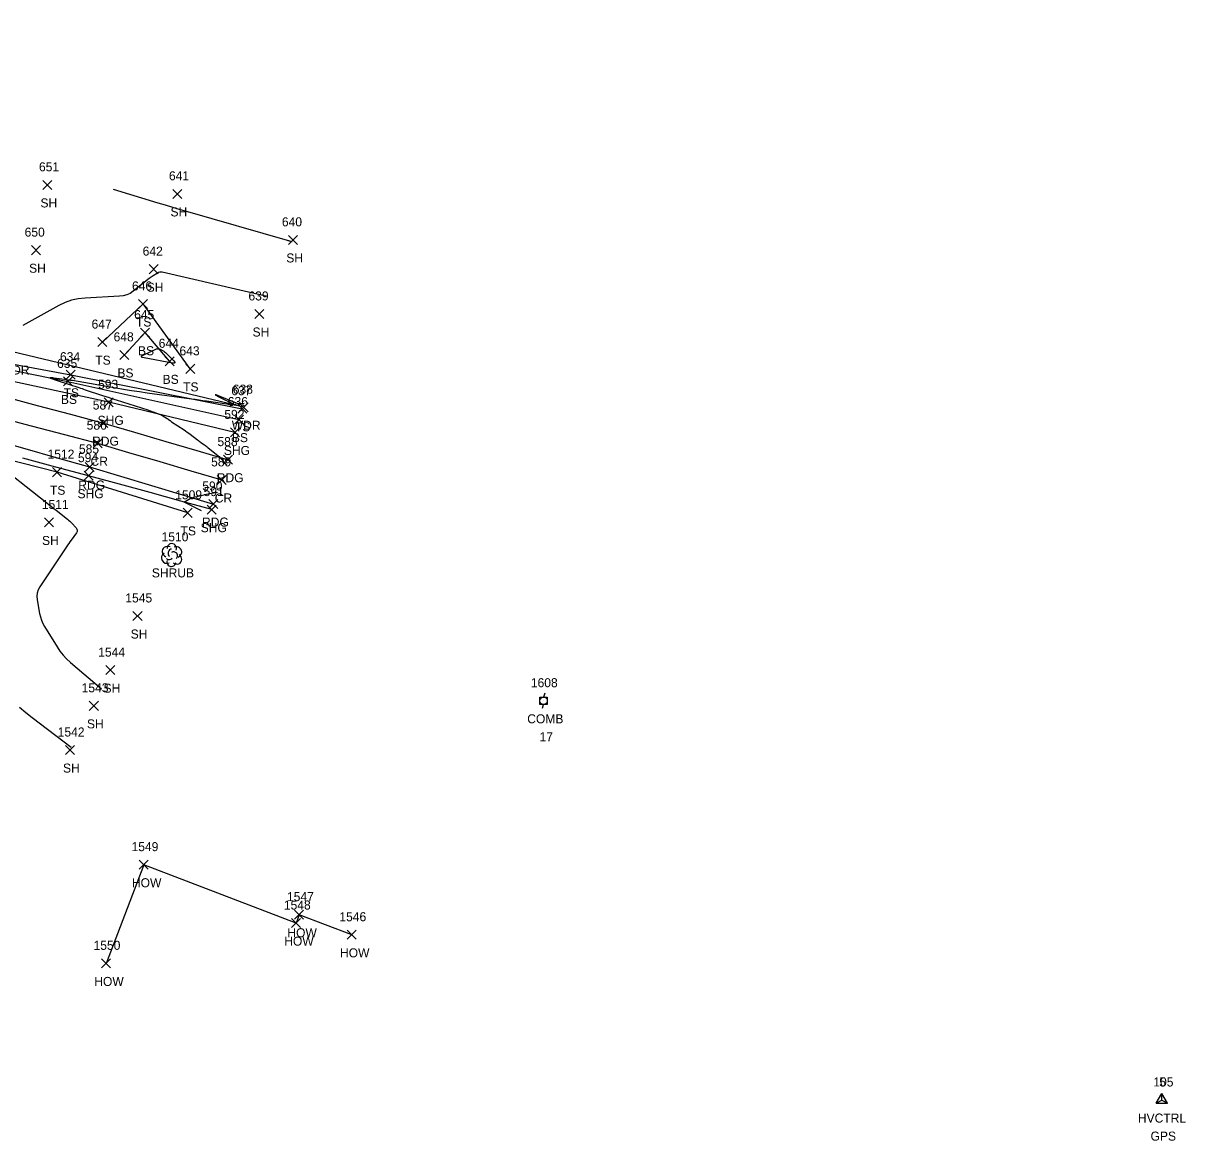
# Model space of a CAD drawing. Extents: x 1592612 to 1596497, y 111838 to 113741.
# Drawn here: x 1593120.8 to 1593378.4, y 113212.6 to 113460.3 of the extents above; entities that cross this region are included whole.
import ezdxf

# ---------------------------------------------------------------- set-up
doc = ezdxf.new("R2010")
doc.units = 0
for name, color, linetype in [('C_A', 7, 'Continuous'), ('C_C', 7, 'Continuous'), ('C_I', 7, 'Continuous'), ('CPSM', 7, 'Continuous'), ('L_A', 7, 'Continuous'), ('L_I', 7, 'Continuous'), ('L_TIC', 7, 'Continuous'), ('LAWA', 7, 'Continuous'), ('LBC', 7, 'Continuous'), ('LELB', 7, 'Continuous'), ('LSH', 7, 'Continuous'), ('LSOGCMA', 7, 'Continuous'), ('LSOGCMI', 7, 'Continuous'), ('P_A', 7, 'Continuous'), ('P_I', 7, 'Continuous'), ('P_TIC', 7, 'Continuous'), ('PEU', 7, 'Continuous'), ('PRC', 7, 'Continuous'), ('PSU', 7, 'Continuous'), ('U_A', 7, 'Continuous'), ('U_C', 7, 'Continuous'), ('U_I', 7, 'Continuous'), ('UP', 7, 'Continuous')]:
    doc.layers.add(name, color=color, linetype=linetype)

msp = doc.modelspace()

# ---------------------------------------------------------------- linework, layer by layer
at = {"layer": 'CPSM'}
for p, q in [((1593371.86, 113220.91), (1593373.11, 113223.08)), ((1593371.86, 113220.91), (1593373.11, 113223.08)), ((1593374.36, 113220.91), (1593373.11, 113223.08)), ((1593373.11, 113221.63), (1593373.11, 113223.08)), ((1593374.36, 113220.91), (1593373.11, 113223.08)), ((1593373.11, 113221.63), (1593373.11, 113223.08)), ((1593371.86, 113220.91), (1593373.11, 113221.63)), ((1593371.86, 113220.91), (1593373.11, 113221.63)), ((1593371.86, 113220.91), (1593374.36, 113220.91)), ((1593371.86, 113220.91), (1593374.36, 113220.91)), ((1593373.11, 113221.63), (1593373.11, 113221.63)), ((1593373.11, 113221.63), (1593374.36, 113220.91)), ((1593373.11, 113221.63), (1593373.11, 113221.63)), ((1593373.11, 113221.63), (1593374.36, 113220.91))]:
    msp.add_line(p, q, dxfattribs=at)
at = {"layer": 'L_TIC'}
for points in [[(1593125.09, 113423.44), (1593127.09, 113425.44)], [(1593127.09, 113423.44), (1593125.09, 113425.44)], [(1593153.9, 113421.45), (1593155.9, 113423.45)], [(1593155.9, 113421.45), (1593153.9, 113423.45)], [(1593179.57, 113411.25), (1593181.57, 113413.25)], [(1593181.57, 113411.25), (1593179.57, 113413.25)], [(1593122.56, 113408.97), (1593124.56, 113410.97)], [(1593124.56, 113408.97), (1593122.56, 113410.97)], [(1593148.63, 113404.76), (1593150.63, 113406.76)], [(1593150.63, 113404.76), (1593148.63, 113406.76)], [(1593146.33, 113397.05), (1593148.33, 113399.05)], [(1593148.33, 113397.05), (1593146.33, 113399.05)], [(1593172.09, 113394.83), (1593174.09, 113396.83)], [(1593174.09, 113394.83), (1593172.09, 113396.83)], [(1593146.75, 113390.69), (1593148.75, 113392.69)], [(1593148.75, 113390.69), (1593146.75, 113392.69)], [(1593137.31, 113388.59), (1593139.31, 113390.59)], [(1593139.31, 113388.59), (1593137.31, 113390.59)], [(1593142.19, 113385.76), (1593144.19, 113387.76)], [(1593144.19, 113385.76), (1593142.19, 113387.76)], [(1593152.19, 113384.34), (1593154.19, 113386.34)], [(1593154.19, 113384.34), (1593152.19, 113386.34)], [(1593156.78, 113382.67), (1593158.78, 113384.67)], [(1593158.78, 113382.67), (1593156.78, 113384.67)], [(1593129.66, 113379.88), (1593131.66, 113381.88)], [(1593131.66, 113379.88), (1593129.66, 113381.88)], [(1593130.3, 113381.36), (1593132.3, 113383.36)], [(1593132.3, 113381.36), (1593130.3, 113383.36)], [(1593168.28, 113373.83), (1593170.28, 113375.83)], [(1593170.28, 113373.83), (1593168.28, 113375.83)], [(1593168.61, 113374.17), (1593170.61, 113376.17)], [(1593170.61, 113374.17), (1593168.61, 113376.17)], [(1593167.55, 113371.43), (1593169.55, 113373.43)], [(1593169.55, 113371.43), (1593167.55, 113373.43)], [(1593127.27, 113359.77), (1593129.27, 113361.77)], [(1593129.27, 113359.77), (1593127.27, 113361.77)], [(1593125.43, 113348.63), (1593127.43, 113350.63)], [(1593127.43, 113348.63), (1593125.43, 113350.63)], [(1593156.22, 113350.76), (1593158.22, 113352.76)], [(1593158.22, 113350.76), (1593156.22, 113352.76)], [(1593145.08, 113327.9), (1593147.08, 113329.9)], [(1593147.08, 113327.9), (1593145.08, 113329.9)], [(1593139.06, 113315.9), (1593141.06, 113317.9)], [(1593141.06, 113315.9), (1593139.06, 113317.9)], [(1593135.4, 113307.99), (1593137.4, 113309.99)], [(1593137.4, 113307.99), (1593135.4, 113309.99)], [(1593130.09, 113298.19), (1593132.09, 113300.19)], [(1593132.09, 113298.19), (1593130.09, 113300.19)], [(1593146.46, 113272.78), (1593148.46, 113274.78)], [(1593148.46, 113272.78), (1593146.46, 113274.78)], [(1593180.9, 113261.7), (1593182.9, 113263.7)], [(1593182.9, 113261.7), (1593180.9, 113263.7)], [(1593180.21, 113259.84), (1593182.21, 113261.84)], [(1593182.21, 113259.84), (1593180.21, 113261.84)], [(1593192.57, 113257.25), (1593194.57, 113259.25)], [(1593194.57, 113257.25), (1593192.57, 113259.25)], [(1593138.12, 113250.91), (1593140.12, 113252.91)], [(1593140.12, 113250.91), (1593138.12, 113252.91)]]:
    msp.add_lwpolyline(points, dxfattribs=at)
at = {"layer": 'LAWA'}
msp.add_lwpolyline([(1593169.61, 113375.17), (1593118.4, 113387.41), (1593080.14, 113394.18), (1593050.56, 113403.45), (1593019.72, 113413.06), (1592995.66, 113420.84), (1592970.68, 113431.18), (1592941.87, 113445.58), (1592917.88, 113456.29)], dxfattribs=at)
at = {"layer": 'LBC'}
msp.add_lwpolyline([(1593193.57, 113258.25), (1593181.9, 113262.7), (1593181.21, 113260.84), (1593147.46, 113273.78), (1593139.11, 113251.91)], dxfattribs=at)
at = {"layer": 'LELB'}
for points in [[(1592908.46, 113460.26), (1592922.6, 113449.57), (1592933.27, 113441.55), (1592945.1, 113436.53), (1592970.28, 113425.51), (1592997.08, 113416.4), (1593023.64, 113407.83), (1593049.42, 113399.69), (1593079.2, 113391.84), (1593097.27, 113387.67), (1593130.66, 113380.88), (1593168.55, 113372.43)], [(1592945.37, 113437.3), (1592970.42, 113426.1), (1592997.18, 113416.81), (1593023.77, 113408.41), (1593049.59, 113400.84), (1593079.37, 113392.64), (1593097.5, 113388.59), (1593131.3, 113382.36), (1593169.28, 113374.83)], [(1593157.78, 113383.67), (1593147.33, 113398.05), (1593138.31, 113389.59)], [(1593153.19, 113385.34), (1593147.75, 113391.69), (1593143.19, 113386.76)], [(1593157.22, 113351.76), (1593128.27, 113360.77), (1593100.02, 113367.91), (1593070.22, 113374.84), (1593038.27, 113383.44), (1593013.97, 113383.15), (1593000.04, 113371.42), (1592985.82, 113350.73), (1592975.86, 113332.67)]]:
    msp.add_lwpolyline(points, dxfattribs=at)
at = {"layer": 'LSH'}
msp.add_line((1593153.62, 113342.45), (1593153.62, 113342.45), dxfattribs=at)
msp.add_line((1593153.62, 113342.45), (1593153.62, 113342.45), dxfattribs=at)
msp.add_arc((1593153.67, 113343.89), 1.05, 335.5272, 180.9563, dxfattribs=at)
for centre, major_axis, ratio, start_param, end_param in [((1593152.83, 113343.12), (1.21, -0.51), 0.895232, 1.570796, 4.712389), ((1593153.41, 113342.91), (-0.208, -0.792), 0.645439, 3.141593, 6.283185), ((1593154.12, 113342.29), (-0.5, 0.667), 0.989748, 3.141593, 6.283185), ((1593154.66, 113343.04), (-1.14, -0.48), 0.949671, 1.570796, 4.712389), ((1593152.54, 113341.75), (0.58, -1.04), 0.959034, 3.141593, 6.283185), ((1593153.62, 113340.95), (0.26, 1.06), 0.942809, 1.570796, 4.712389), ((1593153.16, 113341.7), (-0.625, -0.083), 0.423636, 0, 3.141593), ((1593154.62, 113341.62), (-1.09, 0.79), 0.841452, 1.570796, 4.712389)]:
    msp.add_ellipse(centre, major_axis=major_axis, ratio=ratio, start_param=start_param, end_param=end_param, dxfattribs=at)
at = {"layer": 'LSOGCMA'}
for points in [[(1593180.39, 113411.85), (1593179.76, 113411.99), (1593179.66, 113412.02), (1593179.55, 113412.04), (1593179.45, 113412.07), (1593179.34, 113412.1), (1593157.25, 113418.45), (1593155.59, 113418.93), (1593153.94, 113419.41), (1593152.29, 113419.91), (1593150.64, 113420.41), (1593140.75, 113423.43)], [(1593131.39, 113299.75), (1593122.75, 113306.36), (1593121.33, 113307.47), (1593119.93, 113308.62)]]:
    msp.add_lwpolyline(points, dxfattribs=at)
at = {"layer": 'LSOGCMI'}
for points in [[(1593174.85, 113399.69), (1593151.53, 113405.06), (1593151.26, 113405.1), (1593151.01, 113405.08), (1593150.76, 113405.01), (1593150.52, 113404.89), (1593149.58, 113404.31), (1593149.35, 113404.16), (1593149.12, 113404.01), (1593148.89, 113403.85), (1593148.67, 113403.68), (1593145.12, 113400.87), (1593144.43, 113400.4), (1593143.7, 113400.06), (1593142.92, 113399.84), (1593142.1, 113399.74), (1593134.46, 113399.36), (1593132.92, 113399.2), (1593131.44, 113398.87), (1593130.01, 113398.36), (1593128.62, 113397.69), (1593120.68, 113393.25)], [(1593169.75, 113376.02), (1593168.94, 113375.89), (1593168.81, 113375.87), (1593168.67, 113375.88), (1593168.54, 113375.9), (1593168.41, 113375.94), (1593164.01, 113377.68), (1593163.48, 113377.88), (1593163.3, 113377.93), (1593163.46, 113377.82), (1593163.95, 113377.56), (1593167.58, 113375.75), (1593167.72, 113375.67), (1593167.76, 113375.62), (1593167.7, 113375.6), (1593167.54, 113375.62), (1593166.7, 113375.73), (1593166.49, 113375.76), (1593166.28, 113375.79), (1593166.07, 113375.82), (1593165.86, 113375.85), (1593161.36, 113376.49), (1593160.53, 113376.61), (1593159.71, 113376.73), (1593158.89, 113376.84), (1593158.07, 113376.95), (1593148.25, 113378.3), (1593146.5, 113378.54), (1593144.75, 113378.81), (1593143, 113379.09), (1593141.26, 113379.38), (1593131.66, 113381.05), (1593131.23, 113381.12), (1593130.79, 113381.19), (1593130.36, 113381.25), (1593129.93, 113381.31), (1593127.5, 113381.63), (1593127.41, 113381.64), (1593127.32, 113381.65), (1593127.24, 113381.66), (1593127.15, 113381.67), (1593126.8, 113381.69), (1593126.73, 113381.69), (1593126.71, 113381.68), (1593126.73, 113381.67), (1593126.79, 113381.64), (1593128.26, 113381.12), (1593128.32, 113381.1), (1593128.39, 113381.08), (1593128.45, 113381.06), (1593128.51, 113381.03), (1593133.09, 113379.51), (1593133.44, 113379.4), (1593133.78, 113379.28), (1593134.13, 113379.17), (1593134.48, 113379.05), (1593138.3, 113377.79), (1593139.06, 113377.54), (1593139.81, 113377.29), (1593140.57, 113377.05), (1593141.32, 113376.8), (1593148.36, 113374.56), (1593148.65, 113374.46), (1593148.95, 113374.36), (1593149.25, 113374.25), (1593149.54, 113374.15), (1593150.89, 113373.64), (1593151.1, 113373.56), (1593151.29, 113373.47), (1593151.49, 113373.37), (1593151.68, 113373.26), (1593152.62, 113372.67), (1593152.7, 113372.62), (1593152.79, 113372.56), (1593152.88, 113372.5), (1593152.96, 113372.44), (1593153.3, 113372.19), (1593153.39, 113372.13), (1593153.47, 113372.07), (1593153.56, 113372.01), (1593153.65, 113371.95), (1593156.4, 113370.14), (1593156.75, 113369.91), (1593157.09, 113369.67), (1593157.43, 113369.42), (1593157.77, 113369.17), (1593159.4, 113367.91), (1593159.58, 113367.76), (1593159.77, 113367.62), (1593159.96, 113367.49), (1593160.15, 113367.35), (1593160.93, 113366.82), (1593161.12, 113366.68), (1593161.31, 113366.54), (1593161.49, 113366.4), (1593161.68, 113366.25), (1593163.94, 113364.42), (1593164.15, 113364.23), (1593164.35, 113364.04), (1593164.54, 113363.84), (1593164.72, 113363.63), (1593165.78, 113362.34)], [(1593113.6, 113363.74), (1593125.99, 113353.95), (1593126.5, 113353.55), (1593127.01, 113353.15), (1593127.52, 113352.75), (1593128.03, 113352.35), (1593130.55, 113350.38), (1593130.81, 113350.16), (1593131.07, 113349.93), (1593131.32, 113349.7), (1593131.56, 113349.45), (1593132.48, 113348.42), (1593132.66, 113348.17), (1593132.73, 113347.9), (1593132.69, 113347.63), (1593132.54, 113347.36), (1593131.36, 113345.73), (1593131.09, 113345.36), (1593130.83, 113344.99), (1593130.58, 113344.62), (1593130.32, 113344.24), (1593124.41, 113335.35), (1593124.05, 113334.69), (1593123.83, 113333.99), (1593123.76, 113333.27), (1593123.82, 113332.51), (1593124.38, 113329.43), (1593124.55, 113328.68), (1593124.79, 113327.95), (1593125.1, 113327.24), (1593125.47, 113326.57), (1593128.26, 113322.05), (1593128.9, 113321.11), (1593129.6, 113320.22), (1593130.37, 113319.39), (1593131.21, 113318.62), (1593138.13, 113312.73)], [(1593160.3, 113352.17), (1593156.44, 113354.14), (1593156.42, 113354.15), (1593156.41, 113354.16), (1593156.42, 113354.18), (1593156.44, 113354.19), (1593156.54, 113354.24), (1593156.56, 113354.26), (1593156.59, 113354.27), (1593156.61, 113354.28), (1593156.64, 113354.3), (1593157.73, 113354.92), (1593157.92, 113355.02), (1593158.12, 113355.11), (1593158.33, 113355.18), (1593158.54, 113355.24), (1593160.8, 113355.76), (1593161.1, 113355.83), (1593161.4, 113355.89), (1593161.7, 113355.96), (1593162.01, 113356.01), (1593163.82, 113356.36)]]:
    msp.add_lwpolyline(points, dxfattribs=at)
msp.add_lwpolyline([(1593152.07, 113387.45), (1593152.25, 113387.32), (1593152.42, 113387.17), (1593152.59, 113387.02), (1593154.13, 113385.42), (1593154.35, 113385.15), (1593154.38, 113384.98), (1593154.22, 113384.9), (1593153.87, 113384.94), (1593147.54, 113386.09), (1593147.1, 113386.22), (1593146.94, 113386.38), (1593147.06, 113386.57), (1593147.46, 113386.79), (1593150.28, 113388.07), (1593150.49, 113388.14), (1593150.69, 113388.15), (1593150.89, 113388.12), (1593151.09, 113388.03), (1593151.88, 113387.57)], close=True, dxfattribs=at)
at = {"layer": 'P_TIC'}
for points in [[(1593138.7, 113375.26), (1593140.7, 113377.26)], [(1593140.7, 113375.26), (1593138.7, 113377.26)], [(1593137.52, 113370.65), (1593139.52, 113372.65)], [(1593139.52, 113370.65), (1593137.52, 113372.65)], [(1593166.68, 113368.58), (1593168.68, 113370.58)], [(1593168.68, 113368.58), (1593166.68, 113370.58)], [(1593136.23, 113366.19), (1593138.23, 113368.19)], [(1593138.23, 113366.19), (1593136.23, 113368.19)], [(1593165.16, 113362.54), (1593167.16, 113364.54)], [(1593167.16, 113362.54), (1593165.16, 113364.54)], [(1593134.25, 113358.99), (1593136.25, 113360.99)], [(1593136.25, 113358.99), (1593134.25, 113360.99)], [(1593134.46, 113360.92), (1593136.46, 113362.92)], [(1593136.46, 113360.92), (1593134.46, 113362.92)], [(1593163.76, 113358.05), (1593165.76, 113360.05)], [(1593165.76, 113358.05), (1593163.76, 113360.05)], [(1593161.54, 113351.47), (1593163.54, 113353.47)], [(1593163.54, 113351.47), (1593161.54, 113353.47)], [(1593161.89, 113352.71), (1593163.89, 113354.71)], [(1593163.89, 113352.71), (1593161.89, 113354.71)]]:
    msp.add_lwpolyline(points, dxfattribs=at)
at = {"layer": 'PEU'}
for points in [[(1593116.55, 113377.54), (1593123.87, 113375.58), (1593131.2, 113373.62), (1593138.52, 113371.65), (1593145.43, 113369.62), (1593152.34, 113367.59), (1593159.25, 113365.57), (1593166.16, 113363.54)], [(1593113.91, 113368.02), (1593121.1, 113365.99), (1593128.28, 113363.95), (1593135.46, 113361.92), (1593142.32, 113359.87), (1593149.17, 113357.82), (1593156.03, 113355.76), (1593162.89, 113353.71)]]:
    msp.add_lwpolyline(points, dxfattribs=at)
at = {"layer": 'PRC'}
msp.add_lwpolyline([(1593115.17, 113372.97), (1593122.53, 113371.04), (1593129.88, 113369.12), (1593137.23, 113367.19), (1593144.11, 113365.16), (1593151, 113363.12), (1593157.88, 113361.08), (1593164.76, 113359.05)], dxfattribs=at)
at = {"layer": 'PSU'}
for points in [[(1593167.68, 113369.58), (1593139.7, 113376.26), (1593109.82, 113382.7), (1593081.74, 113389.18), (1593053.82, 113397.15), (1593024.82, 113405.62), (1592996.75, 113414.7), (1592967.82, 113425.18), (1592940.2, 113435.64), (1592911.84, 113443.03)], [(1593162.54, 113352.47), (1593155.72, 113354.35), (1593148.89, 113356.23), (1593142.07, 113358.11), (1593135.25, 113359.99), (1593127.96, 113361.91), (1593120.67, 113363.84)]]:
    msp.add_lwpolyline(points, dxfattribs=at)
at = {"layer": 'UP'}
for p, q in [((1593235.24, 113309.27), (1593235.24, 113310.94)), ((1593235.24, 113310.94), (1593236.91, 113310.94)), ((1593236.33, 113311.77), (1593236.08, 113310.94)), ((1593236.08, 113310.11), (1593236.08, 113310.11)), ((1593236.91, 113310.94), (1593236.91, 113309.27)), ((1593236.91, 113309.27), (1593235.24, 113309.27)), ((1593235.83, 113308.44), (1593236.08, 113309.27))]:
    msp.add_line(p, q, dxfattribs=at)
msp.add_circle((1593236.08, 113310.11), 0.833, dxfattribs=at)

# ---------------------------------------------------------------- texts
at = {"layer": 'C_A'}
msp.add_text('HVCTRL', height=2, dxfattribs=at).set_placement((1593367.8, 113216.63))
msp.add_text('HVCTRL', height=2, dxfattribs=at).set_placement((1593367.8, 113216.63))
at = {"layer": 'C_C'}
msp.add_text('GPS', height=2, dxfattribs=at).set_placement((1593370.61, 113212.63))
at = {"layer": 'C_I'}
for s, p in [('105', (1593371.23, 113224.63)), ('5', (1593372.54, 113224.63))]:
    msp.add_text(s, height=2, dxfattribs=at).set_placement(p)
at = {"layer": 'L_A'}
for s, p in [('SH', (1593124.57, 113419.44)), ('SH', (1593153.39, 113417.45)), ('SH', (1593179.06, 113407.25)), ('SH', (1593122.05, 113404.97)), ('SH', (1593148.12, 113400.76)), ('TS', (1593145.74, 113393.05)), ('SH', (1593171.58, 113390.83)), ('BS', (1593146.19, 113386.69)), ('WDR', (1593115.76, 113382.41)), ('TS', (1593136.72, 113384.59)), ('BS', (1593141.63, 113381.76)), ('BS', (1593151.64, 113380.34)), ('TS', (1593129.7, 113377.36)), ('TS', (1593156.19, 113378.67)), ('BS', (1593129.1, 113375.88)), ('WDR', (1593166.97, 113370.17)), ('TS', (1593167.69, 113369.83)), ('BS', (1593166.99, 113367.43)), ('TS', (1593126.68, 113355.77)), ('TS', (1593155.62, 113346.76)), ('SH', (1593124.92, 113344.63)), ('SHRUB', (1593149.25, 113337.45)), ('SH', (1593144.57, 113323.9)), ('SH', (1593138.55, 113311.9)), ('SH', (1593134.88, 113303.99)), ('SH', (1593129.57, 113294.19)), ('HOW', (1593144.84, 113268.78)), ('HOW', (1593178.6, 113255.84)), ('HOW', (1593179.29, 113257.7)), ('HOW', (1593190.96, 113253.25)), ('HOW', (1593136.5, 113246.91))]:
    msp.add_text(s, height=2, dxfattribs=at).set_placement(p)
at = {"layer": 'L_I'}
for s, p in [('651', (1593124.24, 113427.44)), ('641', (1593153.05, 113425.45)), ('650', (1593121.06, 113412.97)), ('640', (1593178.08, 113415.25)), ('642', (1593147.22, 113408.76)), ('646', (1593144.86, 113401.05)), ('639', (1593170.67, 113398.83)), ('647', (1593135.9, 113392.59)), ('645', (1593145.34, 113394.69)), ('648', (1593140.78, 113389.76)), ('644', (1593150.78, 113388.34)), ('634', (1593128.89, 113385.36)), ('643', (1593155.38, 113386.67)), ('635', (1593128.25, 113383.88)), ('637', (1593166.87, 113377.83)), ('638', (1593167.2, 113378.17)), ('636', (1593166.09, 113375.43)), ('1512', (1593126.14, 113363.77)), ('1509', (1593154.44, 113354.76)), ('1511', (1593124.87, 113352.63)), ('1510', (1593151.41, 113345.45)), ('1545', (1593143.38, 113331.9)), ('1544', (1593137.37, 113319.9)), ('1543', (1593133.7, 113311.99)), ('1542', (1593128.39, 113302.19)), ('1549', (1593144.76, 113276.78)), ('1548', (1593178.52, 113263.84)), ('1547', (1593179.21, 113265.7)), ('1546', (1593190.82, 113261.25)), ('1550', (1593136.34, 113254.91))]:
    msp.add_text(s, height=2, dxfattribs=at).set_placement(p)
at = {"layer": 'P_A'}
for s, p in [('SHG', (1593137.24, 113371.26)), ('RDG', (1593136.01, 113366.65)), ('SHG', (1593165.22, 113364.58)), ('CR', (1593135.67, 113362.19)), ('RDG', (1593132.95, 113356.92)), ('RDG', (1593163.65, 113358.54)), ('SHG', (1593132.78, 113354.99)), ('CR', (1593163.2, 113354.05)), ('RDG', (1593160.38, 113348.71)), ('SHG', (1593160.08, 113347.47))]:
    msp.add_text(s, height=2, dxfattribs=at).set_placement(p)
at = {"layer": 'P_I'}
for s, p in [('593', (1593137.34, 113379.26)), ('587', (1593136.16, 113374.65)), ('592', (1593165.32, 113372.58)), ('586', (1593134.81, 113370.19)), ('585', (1593133.1, 113364.92)), ('588', (1593163.8, 113366.54)), ('594', (1593132.88, 113362.99)), ('589', (1593162.39, 113362.05)), ('590', (1593160.44, 113356.71)), ('591', (1593160.74, 113355.47))]:
    msp.add_text(s, height=2, dxfattribs=at).set_placement(p)
at = {"layer": 'U_A'}
msp.add_text('COMB', height=2, dxfattribs=at).set_placement((1593232.46, 113305.11))
at = {"layer": 'U_C'}
msp.add_text('17', height=2, dxfattribs=at).set_placement((1593235.18, 113301.11))
at = {"layer": 'U_I'}
msp.add_text('1608', height=2, dxfattribs=at).set_placement((1593233.26, 113313.11))

doc.saveas('drawing.dxf')
